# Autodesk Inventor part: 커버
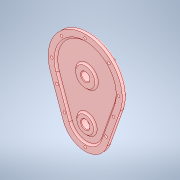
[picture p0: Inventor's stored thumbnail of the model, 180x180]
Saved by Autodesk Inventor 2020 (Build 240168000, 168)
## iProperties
Created: 2024-05
Part Number: 커버
Material: 알루미늄 6061
Document SubType Name: Modeling
Designer: oem
Density: 2.7 g/cm^3
Appearance: 기본값
Author: jhkim
Sending System: Autodesk Inventor 2025
Preprocessor: ST-DEVELOPER v20
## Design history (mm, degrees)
node "커버1"
node "솔리드2"
node "솔리드1"
